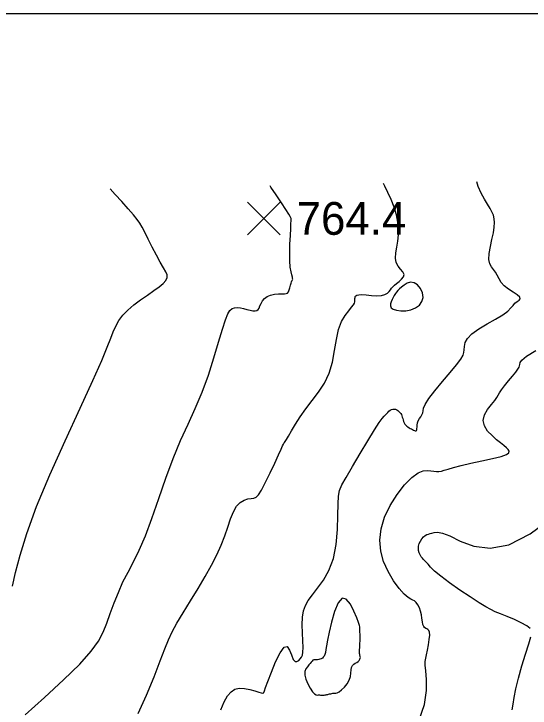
# Model space of a CAD drawing. Extents: x 2566142 to 2571431, y 418755 to 421584.
# Drawn here: x 2568243.6 to 2568479.9, y 421243.9 to 421561.7 of the extents above; entities that cross this region are included whole.
import ezdxf

# ---------------------------------------------------------------- set-up
doc = ezdxf.new("R2010")
doc.units = 0
for name, color, linetype in [('Contour_ADS_Major', 7, 'Continuous'), ('Contour_ADS_Minor', 7, 'Continuous'), ('Contour_ADS_Spot_Elevation', 7, 'Continuous'), ('Contour_ADS_State_Plane_Border', 7, 'Continuous')]:
    doc.layers.add(name, color=color, linetype=linetype)

# ---------------------------------------------------------------- blocks, each defined once
blk = doc.blocks.new('S750')
at = {"layer": 'Contour_ADS_Spot_Elevation'}
for p, q in [((-0.5, 0.498), (0.5, -0.498)), ((-0.498, -0.5), (0.498, 0.5))]:
    blk.add_line(p, q, dxfattribs=at)

msp = doc.modelspace()

# ---------------------------------------------------------------- linework, layer by layer
at = {"layer": 'Contour_ADS_Major'}
msp.add_line((2568401.99, 421268.05), (2568401.99, 421268.05), dxfattribs=at)
for points in [[(2568467.36, 421423.93), (2568469.63, 421425.64), (2568471.08, 421427.07), (2568472.07, 421428.25), (2568472.95, 421429.19), (2568473.96, 421429.95), (2568474.89, 421430.61), (2568475.4, 421431.28), (2568475.16, 421432.06), (2568473.95, 421433.04), (2568472.09, 421434.22), (2568469.99, 421435.59), (2568468.08, 421437.12), (2568466.68, 421438.77), (2568465.68, 421440.46), (2568464.89, 421442.08), (2568464.09, 421443.51), (2568463.15, 421444.7), (2568462.19, 421445.88), (2568461.43, 421447.32), (2568461.06, 421449.3), (2568461.21, 421451.99), (2568461.74, 421455.16), (2568462.43, 421458.45), (2568463.07, 421461.5), (2568463.48, 421464.04), (2568463.61, 421466.13), (2568463.49, 421467.89), (2568463.1, 421469.47), (2568462.45, 421471), (2568461.55, 421472.63), (2568460.41, 421474.51), (2568459.03, 421476.81), (2568457.49, 421479.6), (2568456.11, 421482.66), (2568455.51, 421484.83)], [(2568371.42, 421266.21), (2568372.28, 421265.23), (2568373.14, 421265.17), (2568373.97, 421265.68), (2568374.68, 421266.44), (2568375.25, 421267.2), (2568375.65, 421268.14), (2568375.88, 421269.54), (2568375.94, 421271.67), (2568375.84, 421274.69), (2568375.7, 421278.29), (2568375.63, 421282.04), (2568375.76, 421285.51), (2568376.21, 421288.39), (2568377.04, 421290.85), (2568378.36, 421293.19), (2568380.22, 421295.73), (2568382.63, 421298.74), (2568385.29, 421302.41), (2568387.82, 421306.89), (2568389.85, 421312.37), (2568391.09, 421318.84), (2568391.69, 421325.69), (2568391.9, 421332.13), (2568391.96, 421337.38), (2568392.14, 421340.97), (2568392.66, 421343.55), (2568393.77, 421346.08), (2568395.72, 421349.51), (2568398.63, 421354.48), (2568402.1, 421360.39), (2568405.6, 421366.28), (2568408.63, 421371.24), (2568410.77, 421374.56), (2568412.16, 421376.48), (2568413.03, 421377.51), (2568413.64, 421378.1), (2568414.18, 421378.66), (2568414.71, 421379.23), (2568415.25, 421379.76), (2568415.81, 421380.21), (2568416.4, 421380.54), (2568417.01, 421380.74), (2568417.62, 421380.8), (2568418.23, 421380.72), (2568418.82, 421380.49), (2568419.37, 421380.15), (2568419.87, 421379.73), (2568420.3, 421379.26), (2568420.66, 421378.77), (2568420.95, 421378.24), (2568421.18, 421377.69), (2568421.39, 421377.09), (2568421.57, 421376.44), (2568421.76, 421375.78), (2568421.97, 421375.11), (2568422.23, 421374.49), (2568422.56, 421373.93), (2568422.96, 421373.43), (2568423.41, 421372.98), (2568423.91, 421372.59), (2568424.46, 421372.24), (2568425.02, 421371.94), (2568425.57, 421371.66), (2568426.09, 421371.42), (2568426.56, 421371.2), (2568426.95, 421371.01), (2568427.29, 421370.88), (2568427.56, 421370.82), (2568427.77, 421370.85), (2568427.92, 421371), (2568428.02, 421371.31), (2568428.08, 421371.83), (2568428.13, 421372.57), (2568428.21, 421373.47), (2568428.38, 421374.46), (2568428.71, 421375.46), (2568429.22, 421376.4), (2568429.81, 421377.3), (2568430.36, 421378.17), (2568430.74, 421379.03), (2568430.9, 421379.94), (2568431.16, 421381.15), (2568431.92, 421382.92), (2568433.58, 421385.55), (2568436.36, 421389.16), (2568439.82, 421393.33), (2568443.33, 421397.49), (2568446.27, 421401.06), (2568448.18, 421403.62), (2568449.2, 421405.39), (2568449.61, 421406.72), (2568449.71, 421407.97), (2568449.81, 421409.45), (2568450.21, 421411.18), (2568451.25, 421413.12), (2568453.26, 421415.24), (2568456.39, 421417.48), (2568460.2, 421419.75), (2568464.06, 421421.94), (2568467.36, 421423.93)], [(2568401.99, 421268.05), (2568401.9, 421268.38), (2568401.85, 421268.84), (2568401.83, 421269.49), (2568401.85, 421270.45), (2568401.92, 421271.76), (2568402, 421273.26), (2568402.08, 421274.79), (2568402.13, 421276.14), (2568402.11, 421277.18), (2568402.06, 421277.94), (2568402, 421278.52), (2568401.94, 421279), (2568401.92, 421279.45), (2568401.91, 421279.89), (2568401.93, 421280.31), (2568401.94, 421280.7), (2568401.93, 421281.11), (2568401.79, 421281.79), (2568401.37, 421283.05), (2568400.56, 421285.17), (2568399.27, 421288.24), (2568397.61, 421291.46), (2568395.74, 421293.8), (2568393.82, 421294.24), (2568392, 421292.11), (2568390.35, 421288.1), (2568388.96, 421283.26), (2568387.88, 421278.63), (2568387.16, 421275.04), (2568386.71, 421272.46), (2568386.43, 421270.66), (2568386.21, 421269.38), (2568385.95, 421268.44), (2568385.63, 421267.73), (2568385.24, 421267.2), (2568384.79, 421266.81), (2568384.27, 421266.5), (2568383.7, 421266.27), (2568383.11, 421266.12), (2568382.52, 421266.03), (2568381.94, 421266.02), (2568381.4, 421266.01), (2568380.9, 421265.95), (2568380.46, 421265.78), (2568380.08, 421265.45), (2568379.69, 421264.97), (2568379.24, 421264.36), (2568378.67, 421263.65), (2568377.95, 421262.84), (2568377.24, 421261.87), (2568376.75, 421260.63), (2568376.7, 421259.04), (2568377.21, 421257.08), (2568378.13, 421254.95), (2568379.25, 421252.96), (2568380.35, 421251.39), (2568381.25, 421250.44), (2568381.97, 421250.01), (2568382.55, 421249.9), (2568383.06, 421249.92), (2568383.55, 421249.93), (2568384.02, 421249.9), (2568384.47, 421249.86), (2568384.9, 421249.83), (2568385.31, 421249.84), (2568385.7, 421249.87), (2568386.09, 421249.93), (2568386.47, 421250), (2568386.86, 421250.08), (2568387.26, 421250.16), (2568387.68, 421250.26), (2568388.14, 421250.38), (2568388.64, 421250.51), (2568389.15, 421250.64), (2568389.65, 421250.73), (2568390.12, 421250.74), (2568390.53, 421250.69), (2568390.98, 421250.67), (2568391.58, 421250.84), (2568392.44, 421251.32), (2568393.61, 421252.23), (2568394.92, 421253.49), (2568396.16, 421254.99), (2568397.11, 421256.64), (2568397.62, 421258.31), (2568397.82, 421259.92), (2568397.92, 421261.36), (2568398.11, 421262.53), (2568398.55, 421263.38), (2568399.18, 421263.97), (2568399.89, 421264.41), (2568400.59, 421264.82), (2568401.17, 421265.27), (2568401.63, 421265.77), (2568401.95, 421266.26), (2568402.14, 421266.71), (2568402.21, 421267.1), (2568402.18, 421267.43), (2568402.09, 421267.74), (2568401.99, 421268.05)], [(2568338.37, 421243.13), (2568339.91, 421246.78), (2568341.44, 421249.53), (2568343.01, 421251.42), (2568344.76, 421252.54), (2568346.78, 421253), (2568349.12, 421252.91), (2568351.57, 421252.45), (2568353.85, 421251.84), (2568355.68, 421251.27), (2568356.85, 421250.9), (2568357.48, 421250.73), (2568357.76, 421250.72), (2568357.86, 421250.82), (2568357.97, 421251.05), (2568358.24, 421251.75), (2568358.83, 421253.3), (2568359.88, 421256.1), (2568361.48, 421260.3), (2568363.42, 421265.05), (2568365.43, 421269.26), (2568367.24, 421271.83), (2568368.65, 421272.03), (2568369.73, 421270.49), (2568370.61, 421268.22), (2568371.42, 421266.21)]]:
    msp.add_lwpolyline(points, dxfattribs=at)
at = {"layer": 'Contour_ADS_Minor'}
for points in [[(2568242.96, 421299.72), (2568244.37, 421305.97), (2568246.42, 421313.92), (2568249.49, 421323.89), (2568253.99, 421336.17), (2568260.09, 421350.73), (2568267.06, 421366.28), (2568273.93, 421381.19), (2568279.75, 421393.81), (2568283.8, 421402.94), (2568286.36, 421409.09), (2568287.96, 421413.19), (2568289.11, 421416.16), (2568290.29, 421418.8), (2568291.69, 421421.3), (2568293.45, 421423.71), (2568295.69, 421426.08), (2568298.48, 421428.46), (2568301.61, 421430.78), (2568304.76, 421432.98), (2568307.67, 421434.98), (2568310.08, 421436.73), (2568311.91, 421438.27), (2568313.15, 421439.65), (2568313.76, 421440.93), (2568313.73, 421442.18), (2568313.14, 421443.61), (2568312.06, 421445.47), (2568310.58, 421447.98), (2568308.8, 421451.26), (2568306.9, 421454.96), (2568305.07, 421458.61), (2568303.52, 421461.75), (2568302.35, 421464.05), (2568301.31, 421465.84), (2568300.09, 421467.56), (2568298.34, 421469.67), (2568295.87, 421472.5), (2568292.95, 421475.77), (2568289.99, 421479.03), (2568287.63, 421481.63)], [(2568371.2, 421440.58), (2568371.07, 421441.21), (2568370.8, 421442.18), (2568370.45, 421443.64), (2568370.12, 421445.72), (2568369.91, 421448.58), (2568369.87, 421452.24), (2568369.98, 421456.29), (2568370.15, 421460.22), (2568370.33, 421463.48), (2568370.44, 421465.69), (2568370.5, 421467), (2568370.51, 421467.69), (2568370.49, 421468.05), (2568370.41, 421468.35), (2568370.12, 421468.91), (2568369.42, 421470.04), (2568368.11, 421472.06), (2568366.11, 421475.11), (2568363.7, 421478.77), (2568361.26, 421482.42), (2568360.84, 421483.03)], [(2568367.81, 421365.97), (2568368.39, 421366.88), (2568369.32, 421368.43), (2568370.68, 421370.78), (2568372.46, 421373.8), (2568374.64, 421377.25), (2568377.21, 421380.91), (2568380.08, 421384.63), (2568383.01, 421388.5), (2568385.71, 421392.65), (2568387.89, 421397.24), (2568389.37, 421402.32), (2568390.37, 421407.6), (2568391.21, 421412.68), (2568392.22, 421417.2), (2568393.63, 421420.84), (2568395.27, 421423.66), (2568396.88, 421425.79), (2568398.21, 421427.36), (2568399.06, 421428.49), (2568399.5, 421429.31), (2568399.66, 421429.92), (2568399.69, 421430.42), (2568399.69, 421430.9), (2568399.7, 421431.37), (2568399.76, 421431.82), (2568399.88, 421432.25), (2568400.12, 421432.64), (2568400.59, 421432.95), (2568401.46, 421433.14), (2568402.87, 421433.17), (2568404.91, 421433.02), (2568407.31, 421432.81), (2568409.75, 421432.67), (2568411.88, 421432.75), (2568413.47, 421433.16), (2568414.57, 421433.8), (2568415.35, 421434.58), (2568415.94, 421435.36), (2568416.48, 421436.07), (2568417.08, 421436.73), (2568417.81, 421437.43), (2568418.74, 421438.22), (2568419.91, 421439.15), (2568421.07, 421440.2), (2568421.93, 421441.32), (2568422.18, 421442.45), (2568421.66, 421443.57), (2568420.63, 421444.76), (2568419.48, 421446.15), (2568418.62, 421447.84), (2568418.32, 421449.92), (2568418.47, 421452.31), (2568418.88, 421454.93), (2568419.32, 421457.67), (2568419.61, 421460.46), (2568419.66, 421463.35), (2568419.39, 421466.38), (2568418.74, 421469.64), (2568417.65, 421473.13), (2568416.29, 421476.65), (2568414.83, 421479.97), (2568413.44, 421482.83), (2568412.82, 421484.02)], [(2568248.74, 421240.86), (2568257.58, 421248.71), (2568266.36, 421256.77), (2568273.82, 421264.08), (2568279.04, 421269.92), (2568282.37, 421274.61), (2568284.49, 421278.71), (2568286.08, 421282.78), (2568287.7, 421287.25), (2568289.47, 421292.02), (2568291.42, 421296.89), (2568293.53, 421301.63), (2568295.83, 421306.14), (2568298.3, 421310.82), (2568300.95, 421316.18), (2568303.77, 421322.72), (2568306.74, 421330.76), (2568309.87, 421339.81), (2568313.12, 421349.19), (2568316.47, 421358.2), (2568319.9, 421366.33), (2568323.33, 421373.82), (2568326.65, 421381.07), (2568329.78, 421388.5), (2568332.63, 421396.36), (2568335.17, 421404.19), (2568337.33, 421411.38), (2568339.1, 421417.33), (2568340.46, 421421.58), (2568341.54, 421424.34), (2568342.49, 421425.96), (2568343.48, 421426.81), (2568344.61, 421427.19), (2568345.9, 421427.26), (2568347.3, 421427.08), (2568348.76, 421426.75), (2568350.25, 421426.37), (2568351.69, 421426), (2568352.98, 421425.74), (2568354.04, 421425.68), (2568354.81, 421425.87), (2568355.37, 421426.33), (2568355.8, 421427.03), (2568356.22, 421427.97), (2568356.71, 421429.09), (2568357.37, 421430.29), (2568358.27, 421431.42), (2568359.51, 421432.35), (2568361.11, 421432.97), (2568362.92, 421433.33), (2568364.71, 421433.49), (2568366.26, 421433.54), (2568367.43, 421433.56), (2568368.25, 421433.65), (2568368.82, 421433.9), (2568369.26, 421434.43), (2568369.64, 421435.29), (2568369.97, 421436.35), (2568370.26, 421437.44), (2568370.49, 421438.38), (2568370.67, 421439.03), (2568370.81, 421439.44), (2568370.93, 421439.67), (2568371.03, 421439.82), (2568371.14, 421439.97), (2568371.21, 421440.19), (2568371.2, 421440.58)], [(2568457.84, 421357.09), (2568462.67, 421358.15), (2568466.59, 421359.14), (2568469.05, 421359.99), (2568470.2, 421360.76), (2568470.37, 421361.49), (2568469.89, 421362.25), (2568469.05, 421363.08), (2568467.88, 421364.06), (2568466.39, 421365.27), (2568464.56, 421366.77), (2568462.47, 421368.61), (2568460.46, 421370.74), (2568458.96, 421373.1), (2568458.38, 421375.6), (2568459, 421378.16), (2568460.45, 421380.64), (2568462.22, 421382.87), (2568463.77, 421384.71), (2568464.74, 421386.05), (2568465.33, 421387.13), (2568465.89, 421388.21), (2568466.77, 421389.6), (2568468.22, 421391.48), (2568470.01, 421393.64), (2568471.83, 421395.8), (2568473.36, 421397.66), (2568474.35, 421398.99), (2568474.88, 421399.9), (2568475.09, 421400.59), (2568475.15, 421401.25), (2568475.28, 421402.05), (2568476.09, 421403.24), (2568478.26, 421405.02), (2568482.48, 421407.64)], [(2568300.45, 421241.38), (2568304.28, 421249.86), (2568307.73, 421258.21), (2568310.57, 421265.47), (2568312.68, 421270.97), (2568314.38, 421275.18), (2568316.09, 421278.87), (2568318.22, 421282.8), (2568321.06, 421287.55), (2568324.4, 421292.94), (2568327.9, 421298.6), (2568331.22, 421304.15), (2568334.09, 421309.3), (2568336.5, 421314.06), (2568338.5, 421318.51), (2568340.17, 421322.75), (2568341.56, 421326.8), (2568342.82, 421330.53), (2568344.09, 421333.75), (2568345.51, 421336.3), (2568347.19, 421338.05), (2568348.99, 421339.11), (2568350.74, 421339.66), (2568352.26, 421339.89), (2568353.45, 421340.01), (2568354.47, 421340.41), (2568355.56, 421341.5), (2568356.96, 421343.7), (2568358.82, 421347.25), (2568360.94, 421351.6), (2568363.02, 421356.03), (2568364.75, 421359.82), (2568365.92, 421362.4), (2568366.62, 421363.92), (2568367, 421364.73), (2568367.23, 421365.14), (2568367.46, 421365.47), (2568367.81, 421365.97)], [(2568429, 421238.03), (2568431.56, 421245.56), (2568432.53, 421251.93), (2568432.52, 421257.07), (2568432.15, 421260.92), (2568431.92, 421263.52), (2568431.91, 421265.27), (2568432.09, 421266.69), (2568432.43, 421268.29), (2568432.88, 421270.42), (2568433.34, 421272.88), (2568433.73, 421275.3), (2568433.92, 421277.32), (2568433.86, 421278.69), (2568433.57, 421279.48), (2568433.14, 421279.91), (2568432.63, 421280.15), (2568432.11, 421280.39), (2568431.62, 421280.74), (2568431.18, 421281.31), (2568430.84, 421282.19), (2568430.59, 421283.46), (2568430.4, 421285), (2568430.16, 421286.67), (2568429.79, 421288.34), (2568429.25, 421289.86), (2568428.57, 421291.17), (2568427.8, 421292.22), (2568427, 421292.94), (2568426.2, 421293.35), (2568425.27, 421293.77), (2568424.02, 421294.56), (2568422.29, 421296.12), (2568419.99, 421298.71), (2568417.4, 421302.2), (2568414.89, 421306.37), (2568412.83, 421310.97), (2568411.54, 421315.8), (2568411.13, 421320.8), (2568411.66, 421325.97), (2568413.21, 421331.27), (2568415.77, 421336.63), (2568418.99, 421341.72), (2568422.47, 421346.14), (2568425.8, 421349.51), (2568428.64, 421351.54), (2568430.99, 421352.49), (2568432.92, 421352.72), (2568434.52, 421352.58), (2568435.85, 421352.38), (2568437.02, 421352.24), (2568438.13, 421352.22), (2568439.29, 421352.37), (2568440.63, 421352.75), (2568442.4, 421353.33), (2568444.86, 421354.09), (2568448.29, 421355), (2568452.8, 421356.02), (2568457.84, 421357.09)], [(2568479.93, 421280.32), (2568478.41, 421281.62), (2568475.86, 421283.01), (2568472.68, 421284.45), (2568469.33, 421285.83), (2568466.32, 421287.03), (2568463.94, 421288), (2568461.86, 421288.97), (2568459.57, 421290.25), (2568456.53, 421292.13), (2568452.44, 421294.79), (2568447.74, 421297.96), (2568443.06, 421301.25), (2568439.04, 421304.24), (2568436.16, 421306.64), (2568434.29, 421308.44), (2568433.17, 421309.72), (2568432.5, 421310.56), (2568432.06, 421311.07), (2568431.73, 421311.37), (2568431.42, 421311.61), (2568431.05, 421311.94), (2568430.58, 421312.48), (2568430.04, 421313.2), (2568429.53, 421314.06), (2568429.1, 421315.01), (2568428.83, 421316.01), (2568428.75, 421317.04), (2568428.86, 421318.1), (2568429.18, 421319.2), (2568429.71, 421320.31), (2568430.39, 421321.35), (2568431.15, 421322.26), (2568431.92, 421322.95), (2568432.65, 421323.36), (2568433.37, 421323.59), (2568434.12, 421323.76), (2568434.95, 421323.99), (2568435.97, 421324.32), (2568437.44, 421324.46), (2568439.72, 421324.05), (2568443.12, 421322.72), (2568447.91, 421320.38), (2568454.08, 421318.05), (2568461.54, 421317.04), (2568470.21, 421318.63), (2568479.86, 421323.65), (2568489.79, 421330.93)], [(2568471.65, 421243.08), (2568472.17, 421245.72), (2568472.61, 421248.78), (2568473.34, 421252.68), (2568474.59, 421257.66), (2568476.18, 421263.22), (2568477.84, 421268.65), (2568479.27, 421273.26), (2568480.2, 421276.56)]]:
    msp.add_lwpolyline(points, dxfattribs=at)
msp.add_lwpolyline([(2568425.37, 421426.24), (2568427.46, 421427.11), (2568429.19, 421428.38), (2568430.38, 421429.99), (2568430.88, 421431.88), (2568430.6, 421433.95), (2568429.69, 421435.96), (2568428.34, 421437.62), (2568426.78, 421438.64), (2568425.18, 421438.83), (2568423.65, 421438.36), (2568422.25, 421437.52), (2568421.06, 421436.58), (2568420.13, 421435.76), (2568419.4, 421435.04), (2568418.81, 421434.36), (2568418.27, 421433.62), (2568417.73, 421432.78), (2568417.2, 421431.86), (2568416.71, 421430.89), (2568416.29, 421429.89), (2568415.98, 421428.91), (2568415.93, 421427.99), (2568416.28, 421427.17), (2568417.19, 421426.49), (2568418.75, 421425.98), (2568420.78, 421425.73), (2568423.07, 421425.79), (2568425.37, 421426.24)], close=True, dxfattribs=at)
at = {"layer": 'Contour_ADS_State_Plane_Border'}
msp.add_lwpolyline([(2566164.43, 418777.5), (2571407.81, 418777.5), (2571407.81, 421561.67), (2566164.43, 421561.67), (2566164.43, 418777.5)], close=True, dxfattribs=at)

# ---------------------------------------------------------------- block references
at = {"layer": 'Contour_ADS_Spot_Elevation', "xscale": 15, "yscale": 15}
msp.add_blockref('S750', (2568358.03, 421468.04), dxfattribs=at)

# ---------------------------------------------------------------- texts
at = {"layer": 'Contour_ADS_Spot_Elevation'}
msp.add_text('764.4', height=15, dxfattribs=at).set_placement((2568373.03, 421460.54))

doc.saveas('drawing.dxf')
